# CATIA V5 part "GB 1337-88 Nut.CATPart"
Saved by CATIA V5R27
Part number: GB 1337-88 六角自锁螺母
Bounding box of the stored display mesh (mm): x -9.815 to 9.815, y -8.5 to 8.5, z 0 to 10
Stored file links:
  E:\资料\Catia超级副本\GB 1337-88 六角自锁螺母\GB 1337-88 Nut.CATPart
  E:\资料\Catia超级副本\GB 1337-88 六角自锁螺母\GB1337-88_Nut_DesignTable.xlsx
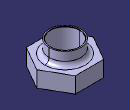
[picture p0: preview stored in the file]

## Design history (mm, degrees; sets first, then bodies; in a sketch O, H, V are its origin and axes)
Parameters
  H = 10 mm {design table}
  h = 5.5 mm {design table}
  d1 = 11 mm {design table}
  r = 1.5 mm {design table}
  S = 17 mm {design table}
  d = 10 mm {design table}
AxisSystem1: origin (0, 0, 0), X (1, 0, 0), Y (0, 1, 0), Z (0, 0, 1)
Set1 "输入条件"
  Plane1: type Normal, Curve Line1, RefPoint Point1, Ratio 0
  Point1: (0, 0, 0), in AxisSystem1
Body1 (main body)
  Sketch1 on Plane1, origin (0, 0, 0), H (1, 0, 0), V (0, 1, 0)
    point P1 (0, 8.5)
    construction circle A1 centre (0, 0) radius 9.815
    construction circle A2 centre (0, 0) radius 8.5
    point P2 (4.9075, 8.5)
    point P3 (-4.9075, 8.5)
    point P4 (-9.815, 0)
    point P5 (-4.9075, -8.5)
    point P6 (4.9075, -8.5)
    point P7 (9.815, 0)
    line L1 (4.9075, 8.5) -> (-4.9075, 8.5)
    line L2 (-4.9075, 8.5) -> (-9.815, 0)
    line L3 (-9.815, 0) -> (-4.9075, -8.5)
    line L4 (-4.9075, -8.5) -> (4.9075, -8.5)
    line L5 (4.9075, -8.5) -> (9.815, 0)
    line L6 (9.815, 0) -> (4.9075, 8.5)
    construction line L7 (0, 0) -> (0, 8.5)
    distance L4 L1 = 17 {= S}
    coincidence: A1 P2, A1 P3, A1 P4, A1 P5, A1 P6, A1 P7
    tangency: A2 L1, A2 L2, A2 L3, A2 L4, A2 L5, A2 L6
    midpoint: P1 L1
    vertical: L7 V
  Pad1: profile Sketch1, direction (0, 0, 1), length 5.5 {= h}
  Sketch2 on end face of Pad1, origin (0, 0, 5.5), H (1, 0, 0), V (0, 1, 0)
    circle A1 centre (0, 0) radius 5.5
    circle A2 centre (0, 0) radius 5
    radius A1 = 5.5 {= d1/2}
    radius A2 = 5 {= d/2}
    concentricity: A2 A1
  Pad2: profile Sketch2, direction (0, 0, 1), length 4.5 {= H -h}
  Fillet1: radius 1.5 {= r}, on edge [end face of Pad1 | face of Pad2 from Sketch2.A1]
  Pocket1: profile end face of Pad1, direction along Line1 reversed, through (limit type 3)
  Chamfer1: length 0.1, angle 45, on edge [end face of Pad2 | face of Pocket1]; edge [face of Pocket1 | start face of Pad1]
  Set2
    Line1: type PtDir, RefPoint Point1, Direction (0, 0, 1), Start 0, End 20
Relations
  design table "GB 1337-88 六角自锁螺母参数表", configuration 6, drives H, h, d1, r, S, d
